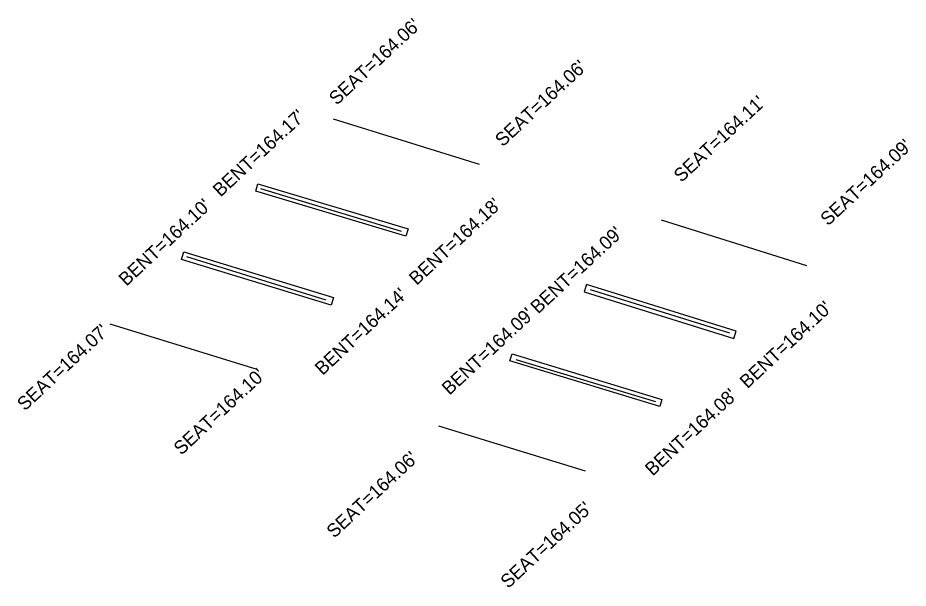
# Model space of a CAD drawing. Extents: x 2107167 to 2121551, y 865392 to 868477.
# Drawn here: x 2107166.9 to 2107431.7, y 865392.1 to 865561.9 of the extents above; entities that cross this region are included whole.
import ezdxf

# ---------------------------------------------------------------- set-up
doc = ezdxf.new("R2010")
doc.units = 0
for name, color, linetype in [('RD_EX_Bridge', 7, 'Continuous'), ('RD_EX_Bridge_txCode', 7, 'Continuous'), ('RD_EX_Conc', 7, 'Continuous')]:
    doc.layers.add(name, color=color, linetype=linetype)

msp = doc.modelspace()

# ---------------------------------------------------------------- linework, layer by layer
at = {"layer": 'RD_EX_Bridge'}
for p, q in [((2107260.72, 865531.84), (2107304.09, 865518.34)), ((2107239.1, 865511.06), (2107280.86, 865498.36)), ((2107358.3, 865501.77), (2107401.5, 865488.14)), ((2107217.03, 865490.91), (2107258.54, 865477.95)), ((2107378.66, 865468), (2107337.25, 865480.91)), ((2107194.29, 865470.81), (2107237.94, 865457.37)), ((2107356.62, 865447.62), (2107315.15, 865460.15)), ((2107292, 865440.5), (2107335.64, 865427.09))]:
    msp.add_line(p, q, dxfattribs=at)
at = {"layer": 'RD_EX_Conc'}
for points in [[(2107282.31, 865496.93), (2107237.64, 865510.28), (2107238.29, 865512.48), (2107282.96, 865499.12)], [(2107260.1, 865476.42), (2107215.56, 865490.02), (2107216.26, 865492.29), (2107260.79, 865478.69)], [(2107335.36, 865480.38), (2107379.84, 865466.5), (2107380.52, 865468.65), (2107336.04, 865482.53)], [(2107357.84, 865446.2), (2107313.27, 865459.79), (2107313.91, 865461.9), (2107358.49, 865448.31)]]:
    msp.add_lwpolyline(points, close=True, dxfattribs=at)

# ---------------------------------------------------------------- texts
at = {"layer": 'RD_EX_Bridge_txCode'}
for s, p in [("SEAT=164.06'", (2107261.72, 865535.7)), ("SEAT=164.06'", (2107311.12, 865523.33)), ("SEAT=164.11'", (2107364.27, 865512.73)), ("BENT=164.17'", (2107227.17, 865508.39)), ("SEAT=164.09'", (2107407.88, 865499.79)), ("BENT=164.10'", (2107199.16, 865481.84)), ("BENT=164.18'", (2107285.52, 865482.1)), ("BENT=164.09'", (2107321.65, 865473.59)), ("BENT=164.14'", (2107257.52, 865455.3)), ("BENT=164.10'", (2107383.9, 865451.37)), ("BENT=164.09'", (2107295.27, 865449.41)), ("SEAT=164.07'", (2107168.95, 865444.72)), ("SEAT=164.10'", (2107215.51, 865431.55)), ("BENT=164.08'", (2107355.71, 865425.35)), ("SEAT=164.06'", (2107260.98, 865406.84)), ("SEAT=164.05'", (2107312.73, 865391.87))]:
    msp.add_text(s, height=4, rotation=42.8914, dxfattribs=at).set_placement(p)

doc.saveas('drawing.dxf')
